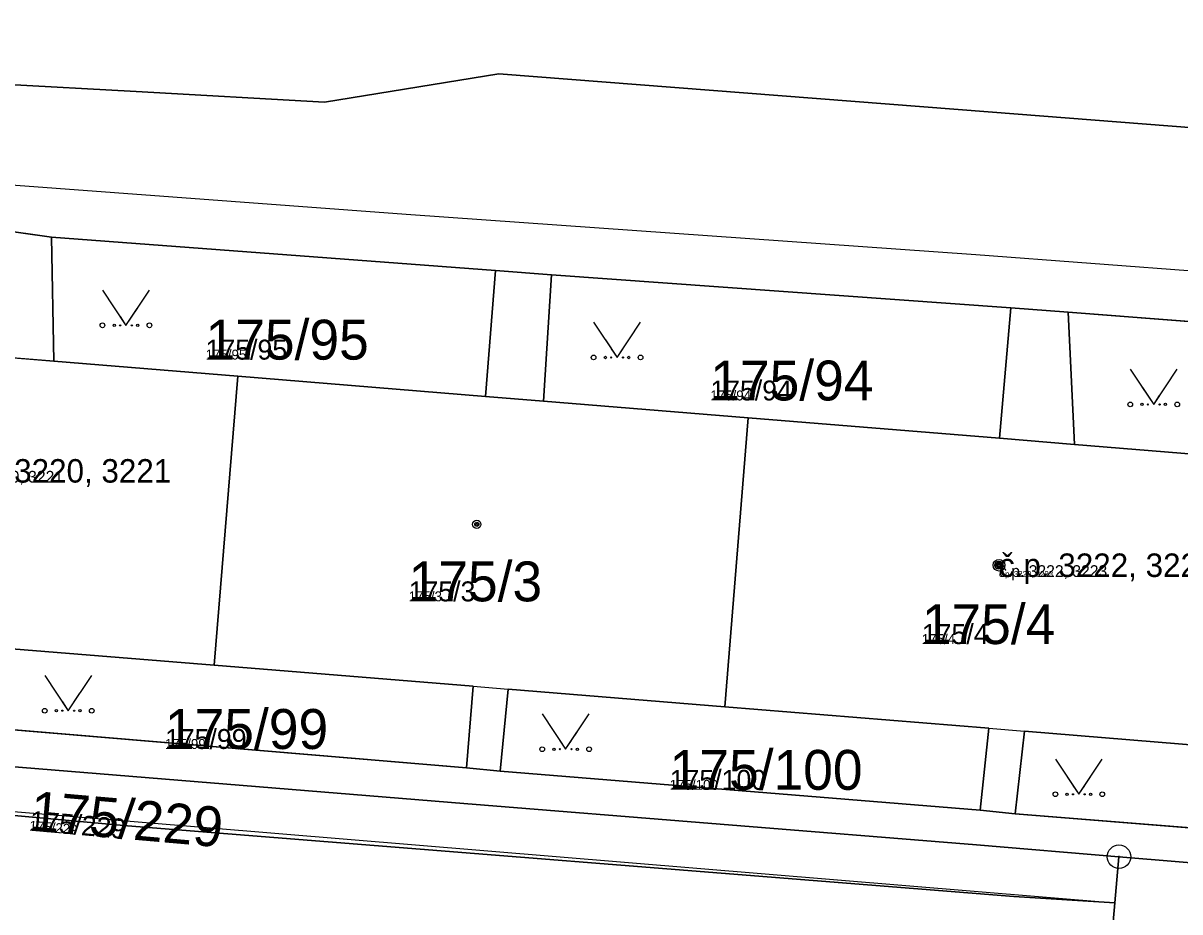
# Model space of a CAD drawing. Extents: x -759873 to -758487, y -975024 to -973516.
# Drawn here: x -759693.9 to -759644.63, y -974733.23 to -974695.36 of the extents above; entities that cross this region are included whole.
import ezdxf

# ---------------------------------------------------------------- set-up
doc = ezdxf.new("R2010")
doc.units = 0
for name, color, linetype in [('KAT_02_hranice parcel', 7, 'Continuous'), ('KAT_03_1000_st čísla parcelní', 7, 'Continuous'), ('KAT_03_1000_čísla parcelní', 7, 'Continuous'), ('KAT_03_1000_čísla popisná', 7, 'Continuous'), ('KAT_03_250_st čísla parcelní', 7, 'Continuous'), ('KAT_03_250_čísla parcelní', 7, 'Continuous'), ('KAT_03_250_čísla popisná', 7, 'Continuous'), ('KAT_03_500_st čísla parcelní', 7, 'Continuous'), ('KAT_03_500_čísla parcelní', 7, 'Continuous'), ('KAT_03_500_čísla popisná', 7, 'Continuous'), ('KAT_04_vnitřní kresba', 7, 'Continuous'), ('KAT_05_1000_značky kultur', 7, 'Continuous'), ('KAT_05_250_značky kultur', 7, 'Continuous'), ('KAT_05_500_značky kultur', 7, 'Continuous'), ('KAT_07_1000_značky budov', 7, 'Continuous'), ('KAT_07_250_značky budov', 7, 'Continuous'), ('KAT_07_500_značky budov', 7, 'Continuous'), ('KAT_11_značky bodu BP', 7, 'Continuous'), ('KAT_14_plocha_budovy', 7, 'Continuous'), ('KAT_14_plocha_pozemek', 7, 'Continuous')]:
    doc.layers.add(name, color=color, linetype=linetype)

msp = doc.modelspace()

# ---------------------------------------------------------------- linework, layer by layer
at = {"layer": 'KAT_02_hranice parcel'}
for p, q in [((-759692.69, -974704.49), (-759695.32, -974704.11)), ((-759692.69, -974704.49), (-759673.78, -974705.9)), ((-759671.39, -974706.09), (-759673.78, -974705.9)), ((-759671.39, -974706.09), (-759651.83, -974707.5)), ((-759649.39, -974707.68), (-759651.83, -974707.5)), ((-759649.39, -974707.68), (-759630.43, -974709.14)), ((-759685.76, -974722.72), (-759684.75, -974710.41)), ((-759664.01, -974724.49), (-759663.01, -974712.18)), ((-759695.14, -974725.4), (-759675.02, -974727.09)), ((-759675.02, -974727.09), (-759673.58, -974727.24)), ((-759673.58, -974727.24), (-759653.14, -974728.9)), ((-759653.14, -974728.9), (-759651.64, -974729.05)), ((-759651.64, -974729.05), (-759631.54, -974730.66)), ((-759647.22, -974730.88), (-759647.39, -974732.84)), ((-759649.17, -974753.04), (-759647.39, -974732.84))]:
    msp.add_line(p, q, dxfattribs=at)
for points in [[(-759468.92, -974710.71), (-759487.56, -974709.31), (-759508.75, -974707.77), (-759512.22, -974711.44), (-759535.41, -974709.44), (-759532.6, -974705.65), (-759589.95, -974700.81), (-759593.89, -974700.48), (-759596.35, -974703.57), (-759627.83, -974701.09), (-759652.61, -974699.15), (-759673.64, -974697.52), (-759681.06, -974698.73), (-759689.09, -974698.27), (-759694.78, -974697.97), (-759700.54, -974697.59)], [(-759684.75, -974710.41), (-759692.59, -974709.77), (-759692.69, -974704.49)], [(-759673.78, -974705.9), (-759674.21, -974711.27), (-759684.75, -974710.41)], [(-759663.01, -974712.18), (-759671.74, -974711.47), (-759671.39, -974706.09)], [(-759651.83, -974707.5), (-759652.31, -974713.05), (-759663.01, -974712.18)], [(-759641.27, -974713.96), (-759649.11, -974713.31), (-759649.39, -974707.68)], [(-759695.14, -974725.4), (-759694.73, -974721.99), (-759685.76, -974722.72)], [(-759685.76, -974722.72), (-759674.73, -974723.62), (-759675.02, -974727.09)], [(-759673.58, -974727.24), (-759673.24, -974723.74), (-759664.01, -974724.49)], [(-759664.01, -974724.49), (-759652.77, -974725.41), (-759653.14, -974728.9)], [(-759647.39, -974732.84), (-759651.7, -974732.58), (-759689.46, -974729.57), (-759713.77, -974727.35), (-759713.66, -974725.35)], [(-759713.66, -974725.35), (-759696.72, -974726.85), (-759675.13, -974728.61), (-759653.29, -974730.38), (-759647.22, -974730.88)], [(-759651.64, -974729.05), (-759651.25, -974725.53), (-759642.27, -974726.27)], [(-759647.22, -974730.88), (-759631.63, -974732.18), (-759609.62, -974733.88), (-759603.65, -974734.41), (-759602.12, -974734.54), (-759585.63, -974736), (-759581.26, -974735.71)]]:
    msp.add_lwpolyline(points, dxfattribs=at)
at = {"layer": 'KAT_03_1000_čísla popisná'}
msp.add_circle((-759652.33, -974718.46), 0.25, dxfattribs=at)
at = {"layer": 'KAT_03_250_čísla popisná'}
msp.add_circle((-759652.33, -974718.46), 0.0625, dxfattribs=at)
at = {"layer": 'KAT_03_500_čísla popisná'}
msp.add_circle((-759652.33, -974718.46), 0.125, dxfattribs=at)
at = {"layer": 'KAT_04_vnitřní kresba'}
for p, q in [((-759697.73, -974702.01), (-759677.59, -974703.5)), ((-759677.59, -974703.5), (-759653.32, -974705.22)), ((-759653.32, -974705.22), (-759630.6, -974706.95)), ((-759695.79, -974709.51), (-759692.59, -974709.77)), ((-759674.21, -974711.27), (-759671.74, -974711.47)), ((-759652.31, -974713.05), (-759649.11, -974713.31)), ((-759674.73, -974723.62), (-759673.24, -974723.74)), ((-759652.77, -974725.41), (-759651.25, -974725.53)), ((-759713.77, -974727.35), (-759647.39, -974732.84))]:
    msp.add_line(p, q, dxfattribs=at)
at = {"layer": 'KAT_05_1000_značky kultur'}
for points in [[(-759690.52, -974706.739), (-759689.52, -974708.24), (-759688.52, -974706.739)], [(-759669.6, -974708.109), (-759668.6, -974709.61), (-759667.6, -974708.109)], [(-759646.74, -974710.109), (-759645.74, -974711.61), (-759644.74, -974710.109)], [(-759692.98, -974723.159), (-759691.98, -974724.66), (-759690.98, -974723.159)], [(-759671.79, -974724.799), (-759670.79, -974726.3), (-759669.79, -974724.799)], [(-759649.93, -974726.719), (-759648.93, -974728.22), (-759647.93, -974726.719)]]:
    msp.add_lwpolyline(points, dxfattribs=at)
for centre in [(-759690.52, -974708.239), (-759688.52, -974708.239), (-759669.6, -974709.609), (-759667.6, -974709.609), (-759646.74, -974711.609), (-759644.74, -974711.609), (-759692.98, -974724.659), (-759690.98, -974724.659), (-759671.79, -974726.299), (-759669.79, -974726.299), (-759649.93, -974728.219), (-759647.93, -974728.219)]:
    msp.add_circle(centre, 0.1, dxfattribs=at)
at = {"layer": 'KAT_05_250_značky kultur'}
for points in [[(-759689.77, -974707.865), (-759689.52, -974708.24), (-759689.27, -974707.865)], [(-759668.85, -974709.235), (-759668.6, -974709.61), (-759668.35, -974709.235)], [(-759645.99, -974711.235), (-759645.74, -974711.61), (-759645.49, -974711.235)], [(-759692.23, -974724.285), (-759691.98, -974724.66), (-759691.73, -974724.285)], [(-759671.04, -974725.925), (-759670.79, -974726.3), (-759670.54, -974725.925)], [(-759649.18, -974727.845), (-759648.93, -974728.22), (-759648.68, -974727.845)]]:
    msp.add_lwpolyline(points, dxfattribs=at)
for centre in [(-759689.77, -974708.24), (-759689.27, -974708.24), (-759668.85, -974709.61), (-759668.35, -974709.61), (-759645.99, -974711.61), (-759645.49, -974711.61), (-759692.23, -974724.66), (-759691.73, -974724.66), (-759671.04, -974726.3), (-759670.54, -974726.3), (-759649.18, -974728.22), (-759648.68, -974728.22)]:
    msp.add_circle(centre, 0.025, dxfattribs=at)
at = {"layer": 'KAT_05_500_značky kultur'}
for points in [[(-759690.02, -974707.49), (-759689.52, -974708.24), (-759689.02, -974707.49)], [(-759669.1, -974708.86), (-759668.6, -974709.61), (-759668.1, -974708.86)], [(-759646.24, -974710.86), (-759645.74, -974711.61), (-759645.24, -974710.86)], [(-759692.48, -974723.91), (-759691.98, -974724.66), (-759691.48, -974723.91)], [(-759671.29, -974725.549), (-759670.79, -974726.3), (-759670.29, -974725.549)], [(-759649.43, -974727.47), (-759648.93, -974728.22), (-759648.43, -974727.47)]]:
    msp.add_lwpolyline(points, dxfattribs=at)
for centre in [(-759690.02, -974708.24), (-759689.02, -974708.24), (-759669.1, -974709.61), (-759668.1, -974709.61), (-759646.24, -974711.61), (-759645.24, -974711.61), (-759692.48, -974724.66), (-759691.48, -974724.66), (-759671.29, -974726.3), (-759670.29, -974726.3), (-759649.43, -974728.22), (-759648.43, -974728.22)]:
    msp.add_circle(centre, 0.05, dxfattribs=at)
at = {"layer": 'KAT_07_1000_značky budov'}
for centre in [(-759674.577, -974716.719), (-759652.337, -974718.459)]:
    msp.add_circle(centre, 0.175, dxfattribs=at)
at = {"layer": 'KAT_07_250_značky budov'}
for centre in [(-759674.572, -974716.72), (-759652.332, -974718.46)]:
    msp.add_circle(centre, 0.0437, dxfattribs=at)
at = {"layer": 'KAT_07_500_značky budov'}
for centre in [(-759674.573, -974716.72), (-759652.333, -974718.46)]:
    msp.add_circle(centre, 0.0875, dxfattribs=at)
at = {"layer": 'KAT_11_značky bodu BP'}
for radius in [0.5, 0.0303]:
    msp.add_circle((-759647.22, -974730.88), radius, dxfattribs=at)
at = {"layer": 'KAT_14_plocha_budovy'}
for points in [[(-759671.74, -974711.47), (-759674.21, -974711.27), (-759684.75, -974710.41), (-759692.59, -974709.77), (-759695.79, -974709.51), (-759706.49, -974708.64), (-759707.49, -974720.95), (-759696.25, -974721.87), (-759694.73, -974721.99), (-759685.76, -974722.72), (-759674.73, -974723.62), (-759673.24, -974723.74), (-759664.01, -974724.49), (-759663.01, -974712.18)], [(-759663.01, -974712.18), (-759664.01, -974724.49), (-759652.77, -974725.41), (-759651.25, -974725.53), (-759642.27, -974726.27), (-759631.25, -974727.17), (-759629.76, -974727.29), (-759620.53, -974728.04), (-759620.43, -974726.84), (-759619.53, -974715.73), (-759628.26, -974715.02), (-759630.73, -974714.82), (-759641.27, -974713.96), (-759649.11, -974713.31), (-759652.31, -974713.05)], [(-759649.17, -974753.04), (-759647.39, -974732.84), (-759651.7, -974732.58), (-759689.46, -974729.57), (-759713.77, -974727.35), (-759726.51, -974725.1), (-759726.59, -974725.59), (-759728.33, -974735.39), (-759728.82, -974738.28), (-759730.01, -974745.03), (-759717.87, -974747.08), (-759715.46, -974747.48), (-759715.33, -974746.83), (-759695.52, -974748.27), (-759688.92, -974747.99), (-759675.67, -974749.13), (-759675.8, -974750.8), (-759653.2, -974752.71)]]:
    msp.add_lwpolyline(points, close=True, dxfattribs=at)
at = {"layer": 'KAT_14_plocha_pozemek'}
for points in [[(-759584.2, -974692.84), (-759605.79, -974691.97), (-759627.85, -974691.09), (-759649.41, -974690.16), (-759671.36, -974688.78), (-759693.02, -974687.37), (-759700.54, -974697.59), (-759694.78, -974697.97), (-759689.09, -974698.27), (-759681.06, -974698.73), (-759673.64, -974697.52), (-759652.61, -974699.15), (-759627.83, -974701.09), (-759596.35, -974703.57)], [(-759596.35, -974703.57), (-759627.83, -974701.09), (-759652.61, -974699.15), (-759673.64, -974697.52), (-759681.06, -974698.73), (-759689.09, -974698.27), (-759694.78, -974697.97), (-759700.54, -974697.59), (-759702.74, -974697.44), (-759724.05, -974696.03)], [(-759721.85, -974701.93), (-759712.7, -974702.91), (-759710.75, -974703.04), (-759695.32, -974704.11), (-759692.69, -974704.49), (-759673.78, -974705.9), (-759671.39, -974706.09), (-759651.83, -974707.5), (-759649.39, -974707.68), (-759630.43, -974709.14), (-759627.92, -974709.32), (-759608.29, -974710.84), (-759605.74, -974711.03)], [(-759588.03, -974734.34), (-759607.69, -974732.58), (-759609.42, -974732.4), (-759630.08, -974730.75), (-759631.54, -974730.66), (-759651.64, -974729.05), (-759653.14, -974728.9), (-759673.58, -974727.24), (-759675.02, -974727.09), (-759695.14, -974725.4), (-759696.95, -974725.28), (-759712.53, -974723.97), (-759710.75, -974703.04), (-759712.7, -974702.91), (-759713.04, -974706.66), (-759713.31, -974710.06), (-759713.45, -974711.78), (-759713.54, -974712.85), (-759714.48, -974723.81), (-759721.48, -974723.21)], [(-759721.81, -974724.63), (-759713.66, -974725.35), (-759696.72, -974726.85), (-759675.13, -974728.61), (-759653.29, -974730.38), (-759647.22, -974730.88), (-759631.63, -974732.18), (-759609.62, -974733.88), (-759603.65, -974734.41)]]:
    msp.add_lwpolyline(points, dxfattribs=at)
for points in [[(-759685.76, -974722.72), (-759684.75, -974710.41), (-759692.59, -974709.77), (-759692.69, -974704.49), (-759695.32, -974704.11), (-759695.79, -974709.51), (-759706.49, -974708.64), (-759707.49, -974720.95), (-759696.25, -974721.87), (-759696.95, -974725.28), (-759695.14, -974725.4), (-759694.73, -974721.99)], [(-759692.69, -974704.49), (-759692.59, -974709.77), (-759684.75, -974710.41), (-759674.21, -974711.27), (-759673.78, -974705.9)], [(-759674.73, -974723.62), (-759675.02, -974727.09), (-759673.58, -974727.24), (-759673.24, -974723.74), (-759664.01, -974724.49), (-759663.01, -974712.18), (-759671.74, -974711.47), (-759671.39, -974706.09), (-759673.78, -974705.9), (-759674.21, -974711.27), (-759684.75, -974710.41), (-759685.76, -974722.72)], [(-759671.39, -974706.09), (-759671.74, -974711.47), (-759663.01, -974712.18), (-759652.31, -974713.05), (-759651.83, -974707.5)], [(-759651.25, -974725.53), (-759642.27, -974726.27), (-759641.27, -974713.96), (-759649.11, -974713.31), (-759649.39, -974707.68), (-759651.83, -974707.5), (-759652.31, -974713.05), (-759663.01, -974712.18), (-759664.01, -974724.49), (-759652.77, -974725.41), (-759653.14, -974728.9), (-759651.64, -974729.05)], [(-759649.39, -974707.68), (-759649.11, -974713.31), (-759641.27, -974713.96), (-759630.73, -974714.82), (-759630.43, -974709.14)], [(-759717.74, -974748.2), (-759709.81, -974749.04), (-759693.97, -974750.34), (-759653.28, -974753.71), (-759653.2, -974752.71), (-759649.17, -974753.04), (-759647.39, -974732.84), (-759651.7, -974732.58), (-759689.46, -974729.57), (-759713.77, -974727.35), (-759713.66, -974725.35), (-759721.81, -974724.63), (-759755.53, -974721.94), (-759761.57, -974738.05), (-759758.82, -974739.02), (-759753.8, -974740.79), (-759753.56, -974740.87), (-759749.15, -974742.25), (-759745.36, -974743.44), (-759743.05, -974744.02), (-759738.11, -974745.25), (-759736.82, -974745.57), (-759724.35, -974747.51), (-759718.05, -974748.17)], [(-759675.02, -974727.09), (-759674.73, -974723.62), (-759685.76, -974722.72), (-759694.73, -974721.99), (-759695.14, -974725.4)], [(-759653.14, -974728.9), (-759652.77, -974725.41), (-759664.01, -974724.49), (-759673.24, -974723.74), (-759673.58, -974727.24)], [(-759647.22, -974730.88), (-759653.29, -974730.38), (-759675.13, -974728.61), (-759696.72, -974726.85), (-759713.66, -974725.35), (-759713.77, -974727.35), (-759689.46, -974729.57), (-759651.7, -974732.58), (-759647.39, -974732.84)], [(-759631.54, -974730.66), (-759631.25, -974727.17), (-759642.27, -974726.27), (-759651.25, -974725.53), (-759651.64, -974729.05)], [(-759560.55, -974760.58), (-759560.5, -974759.95), (-759560.36, -974758.15), (-759559.43, -974745.94), (-759559.31, -974744.32), (-759554.53, -974744.73), (-759554.44, -974743.54), (-759579.98, -974738.48), (-759581.47, -974738.34), (-759581.26, -974735.71), (-759585.63, -974736), (-759602.12, -974734.54), (-759603.65, -974734.41), (-759609.62, -974733.88), (-759631.63, -974732.18), (-759647.22, -974730.88), (-759647.39, -974732.84), (-759649.17, -974753.04), (-759649.25, -974754), (-759646.11, -974754.26), (-759640.37, -974754.73), (-759609.16, -974757.26), (-759572.03, -974760.36), (-759560.6, -974761.29)]]:
    msp.add_lwpolyline(points, close=True, dxfattribs=at)

# ---------------------------------------------------------------- texts
at = {"layer": 'KAT_03_1000_st čísla parcelní'}
for s, p in [('175/3', (-759677.48, -974720)), ('175/4', (-759655.62, -974721.82))]:
    msp.add_text(s, height=1.7, dxfattribs=at).set_placement(p)
at = {"layer": 'KAT_03_1000_čísla parcelní'}
for s, p in [('175/95', (-759686.13, -974709.7)), ('175/94', (-759664.63, -974711.44)), ('175/99', (-759687.86, -974726.289)), ('175/100', (-759666.36, -974728.03))]:
    msp.add_text(s, height=1.7, dxfattribs=at).set_placement(p)
msp.add_text('175/229', height=1.7, rotation=355, dxfattribs=at).set_placement((-759693.654, -974729.766))
at = {"layer": 'KAT_03_1000_čísla popisná'}
for s, p in [('č.p. 3220, 3221', (-759696.81, -974714.94)), ('č.p. 3222, 3223', (-759652.33, -974718.96))]:
    msp.add_text(s, height=1, dxfattribs=at).set_placement(p)
at = {"layer": 'KAT_03_250_st čísla parcelní'}
for s, p in [('175/3', (-759677.48, -974720)), ('175/4', (-759655.62, -974721.82))]:
    msp.add_text(s, height=0.425, dxfattribs=at).set_placement(p)
at = {"layer": 'KAT_03_250_čísla parcelní'}
for s, p in [('175/95', (-759686.13, -974709.7)), ('175/94', (-759664.63, -974711.44)), ('175/99', (-759687.86, -974726.289)), ('175/100', (-759666.36, -974728.03))]:
    msp.add_text(s, height=0.425, dxfattribs=at).set_placement(p)
msp.add_text('175/229', height=0.425, rotation=355, dxfattribs=at).set_placement((-759693.654, -974729.766))
at = {"layer": 'KAT_03_250_čísla popisná'}
msp.add_text('č.p. 3222, 3223', height=0.25, dxfattribs=at).set_placement((-759652.33, -974718.96))
at = {"layer": 'KAT_03_500_st čísla parcelní'}
for s, p in [('175/3', (-759677.48, -974720)), ('175/4', (-759655.62, -974721.82))]:
    msp.add_text(s, height=0.85, dxfattribs=at).set_placement(p)
at = {"layer": 'KAT_03_500_čísla parcelní'}
for s, p in [('175/95', (-759686.13, -974709.7)), ('175/94', (-759664.63, -974711.44)), ('175/99', (-759687.86, -974726.289)), ('175/100', (-759666.36, -974728.03))]:
    msp.add_text(s, height=0.85, dxfattribs=at).set_placement(p)
msp.add_text('175/229', height=0.85, rotation=355, dxfattribs=at).set_placement((-759693.654, -974729.766))
at = {"layer": 'KAT_03_500_čísla popisná'}
for s, p in [('č.p. 3220, 3221', (-759696.81, -974714.94)), ('č.p. 3222, 3223', (-759652.33, -974718.96))]:
    msp.add_text(s, height=0.5, dxfattribs=at).set_placement(p)

doc.saveas('drawing.dxf')
